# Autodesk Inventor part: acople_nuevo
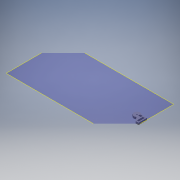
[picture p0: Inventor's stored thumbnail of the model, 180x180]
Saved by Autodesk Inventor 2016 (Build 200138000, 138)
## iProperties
Created: 2017-06
Part Number: acople_nuevo
Material: Generic
Document SubType Name: Modeling
Designer: laboratorioesan
Density: 1 g/cm^3
Appearance: Default
Author: laboratorioesan
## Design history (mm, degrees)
workplane "Work Plane1"
sketch "Sketch1"
  geometry: L1 (428.5, -285.317)-(447, -285.317) reference; L2 (447, -285.317)-(447, -345.317) reference; L3 (447, -345.317)-(428.5, -345.317) reference; L4 (428.5, -345.317)-(428.5, -285.317) reference; L5 (-447, -345.317)-(-447, -285.317) reference; L6 (-447, -285.317)-(-428.5, -285.317) reference; L7 (-428.5, -285.317)-(-428.5, -345.317) reference; L8 (-428.5, -345.317)-(-447, -345.317) reference; L9 (-480.59, -216.985)-(-467, -261.342) reference; L10 (-467, -261.342)-(-467, -375.317) reference; L11 (-467, -375.317)-(-370, -375.317) reference; L12 (-370, -52.817)-(-370, -375.317) reference; L13 (310, 7.183)-(-310, 7.183) reference; L14 (370, -52.817)-(370, -375.317) reference; L15 (370, -375.317)-(467, -375.317) reference; L16 (467, -375.317)-(467, -261.342) reference; L17 (467, -261.342)-(480.59, -216.985) reference; L18 (495.188, 14.837)-(477.824, 115.072) reference; L19 (-427.975, 141.679)-(427.975, 141.679) reference; L20 (-477.824, 115.072)-(-495.188, 14.837) reference; L21 (120, 85.683)-(120, 104.183) reference; L22 (120, 104.183)-(180, 104.183) reference; L23 (180, 104.183)-(180, 85.683) reference; L24 (180, 85.683)-(120, 85.683) reference; L25 (-370, 104.183)-(-370, 85.683) reference; L26 (-370, 85.683)-(-430, 85.683) reference; L27 (-430, 85.683)-(-430, 104.183) reference; L28 (-430, 104.183)-(-370, 104.183) reference; L29 (-180, 85.683)-(-180, 104.183) reference; L30 (-180, 104.183)-(-120, 104.183) reference; L31 (-120, 104.183)-(-120, 85.683) reference; L32 (-120, 85.683)-(-180, 85.683) reference; L33 (370, 85.683)-(370, 104.183) reference; L34 (370, 104.183)-(430, 104.183) reference; L35 (430, 104.183)-(430, 85.683) reference; L36 (430, 85.683)-(370, 85.683) reference; L37 (-400, 55.683)-(-400, 37.183) reference; L38 (-400, 37.183)-(-460, 37.183) reference; L39 (-460, 37.183)-(-460, 55.683) reference; L40 (-460, 55.683)-(-400, 55.683) reference; L41 (-190, 55.683)-(-190, 37.183) reference; L42 (-190, 37.183)-(-250, 37.183) reference; L43 (-250, 37.183)-(-250, 55.683) reference; L44 (-250, 55.683)-(-190, 55.683) reference; L45 (30, 55.683)-(30, 37.183) reference; L46 (30, 37.183)-(-30, 37.183) reference; L47 (-30, 37.183)-(-30, 55.683) reference; L48 (-30, 55.683)-(30, 55.683) reference; L49 (460, 55.683)-(460, 37.183) reference; L50 (460, 37.183)-(400, 37.183) reference; L51 (400, 37.183)-(400, 55.683) reference; L52 (400, 55.683)-(460, 55.683) reference; L53 (250, 55.683)-(250, 37.183) reference; L54 (250, 37.183)-(190, 37.183) reference; L55 (190, 37.183)-(190, 55.683) reference; L56 (190, 55.683)-(250, 55.683) reference; L57 (-526, -95.317)-(-526, -155.317); L58 (-526, -155.317)-(-507.5, -155.317); L59 (-507.5, -155.317)-(-507.5, -95.317); L60 (-507.5, -95.317)-(-526, -95.317); L61 (-497.5, -88.479)-(-497.5, -106.979); L62 (-497.5, -106.979)-(-472.5, -106.979); L63 (-472.5, -106.979)-(-472.5, -88.479); L64 (-472.5, -88.479)-(-497.5, -88.479)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; C1 r 5.25 at (-456, -102.817) reference; C2 r 5.25 at (456, -102.817) reference; C3 r 5.25 at (-456, -102.817); C4 r 5.25 at (-456, -147.817) reference; C5 r 5.25 at (456, -147.817) reference; A1 r 500 centre (-2.526, -70.511) between (-495.188, 14.837) and (-480.59, -216.985) reference; A2 r 60 centre (-310, -52.817) between (-310, 7.183) and (-370, -52.817) reference; A3 r 60 centre (310, -52.817) between (370, -52.817) and (310, 7.183) reference; A4 r 500 centre (2.526, -70.511) between (480.59, -216.985) and (495.188, 14.837) reference; A5 r 60 centre (427.975, 81.679) between (477.824, 115.072) and (427.975, 141.679) reference; A6 r 60 centre (-427.975, 81.679) between (-427.975, 141.679) and (-477.824, 115.072) reference; A7 r 32.5 centre (-456, -102.817) between (-475.816, -128.578) and (-481.617, -82.817); 1 further point
  constraints: 24 end point, 2 centre point, 2 point on circle
extrude "Extrusion1" new body sketch "Sketch1" distance "d0" = 20.5; taper "d1" = 0 deg
body "Solid1"
node "Reference1"
